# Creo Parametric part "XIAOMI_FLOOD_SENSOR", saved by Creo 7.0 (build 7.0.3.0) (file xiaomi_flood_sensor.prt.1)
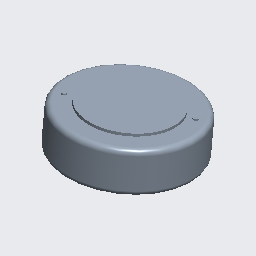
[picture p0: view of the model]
Units: millimeter Kilogram Sec (mmKs); MM, KILOGRAM, SECS

Created from: XX_SOLID_PART_MMKS_ABS.PRT

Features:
  1. coordinate system
  2. datum plane "RIGHT"
  3. datum plane "TOP"
  4. datum plane "FRONT"
  5. extrusion "Extrude 1"
  6. extrusion "Extrude 2"
  7. extrusion "Extrude 3"
  8. round "Round 1"

Surfaces: 4 plane, 4 cylinder, 4 torus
